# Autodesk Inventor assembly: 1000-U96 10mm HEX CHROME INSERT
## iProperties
Created: 2007-03
Part Number: 1000-U96 10mm HEX CHROME INSERT
Document SubType Name: Assembly
Designer: Andy Moles
Translation Standard: STEP AP214IS
File Name: 1000-U96_ASM
Preprocessor: PRO/ENGINEER BY PARAMETRIC TECHNOLOGY CORPORATION, 2003200
Postprocessor: Build: 344b, Release: 11 SP2 - Date: Fri 08/18/2006
Sent Units: MILLIMETERS
Uncertainty: 0.0038593728735789997
Author: Andy Moles
